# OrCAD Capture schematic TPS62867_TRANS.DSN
size D; title: TPS62867 2.4-V to 5.5-V Input, 6-A Synchronous Step-Down; rev: 1.1; note: Datasheet: SLUSDN8           EVM: NA
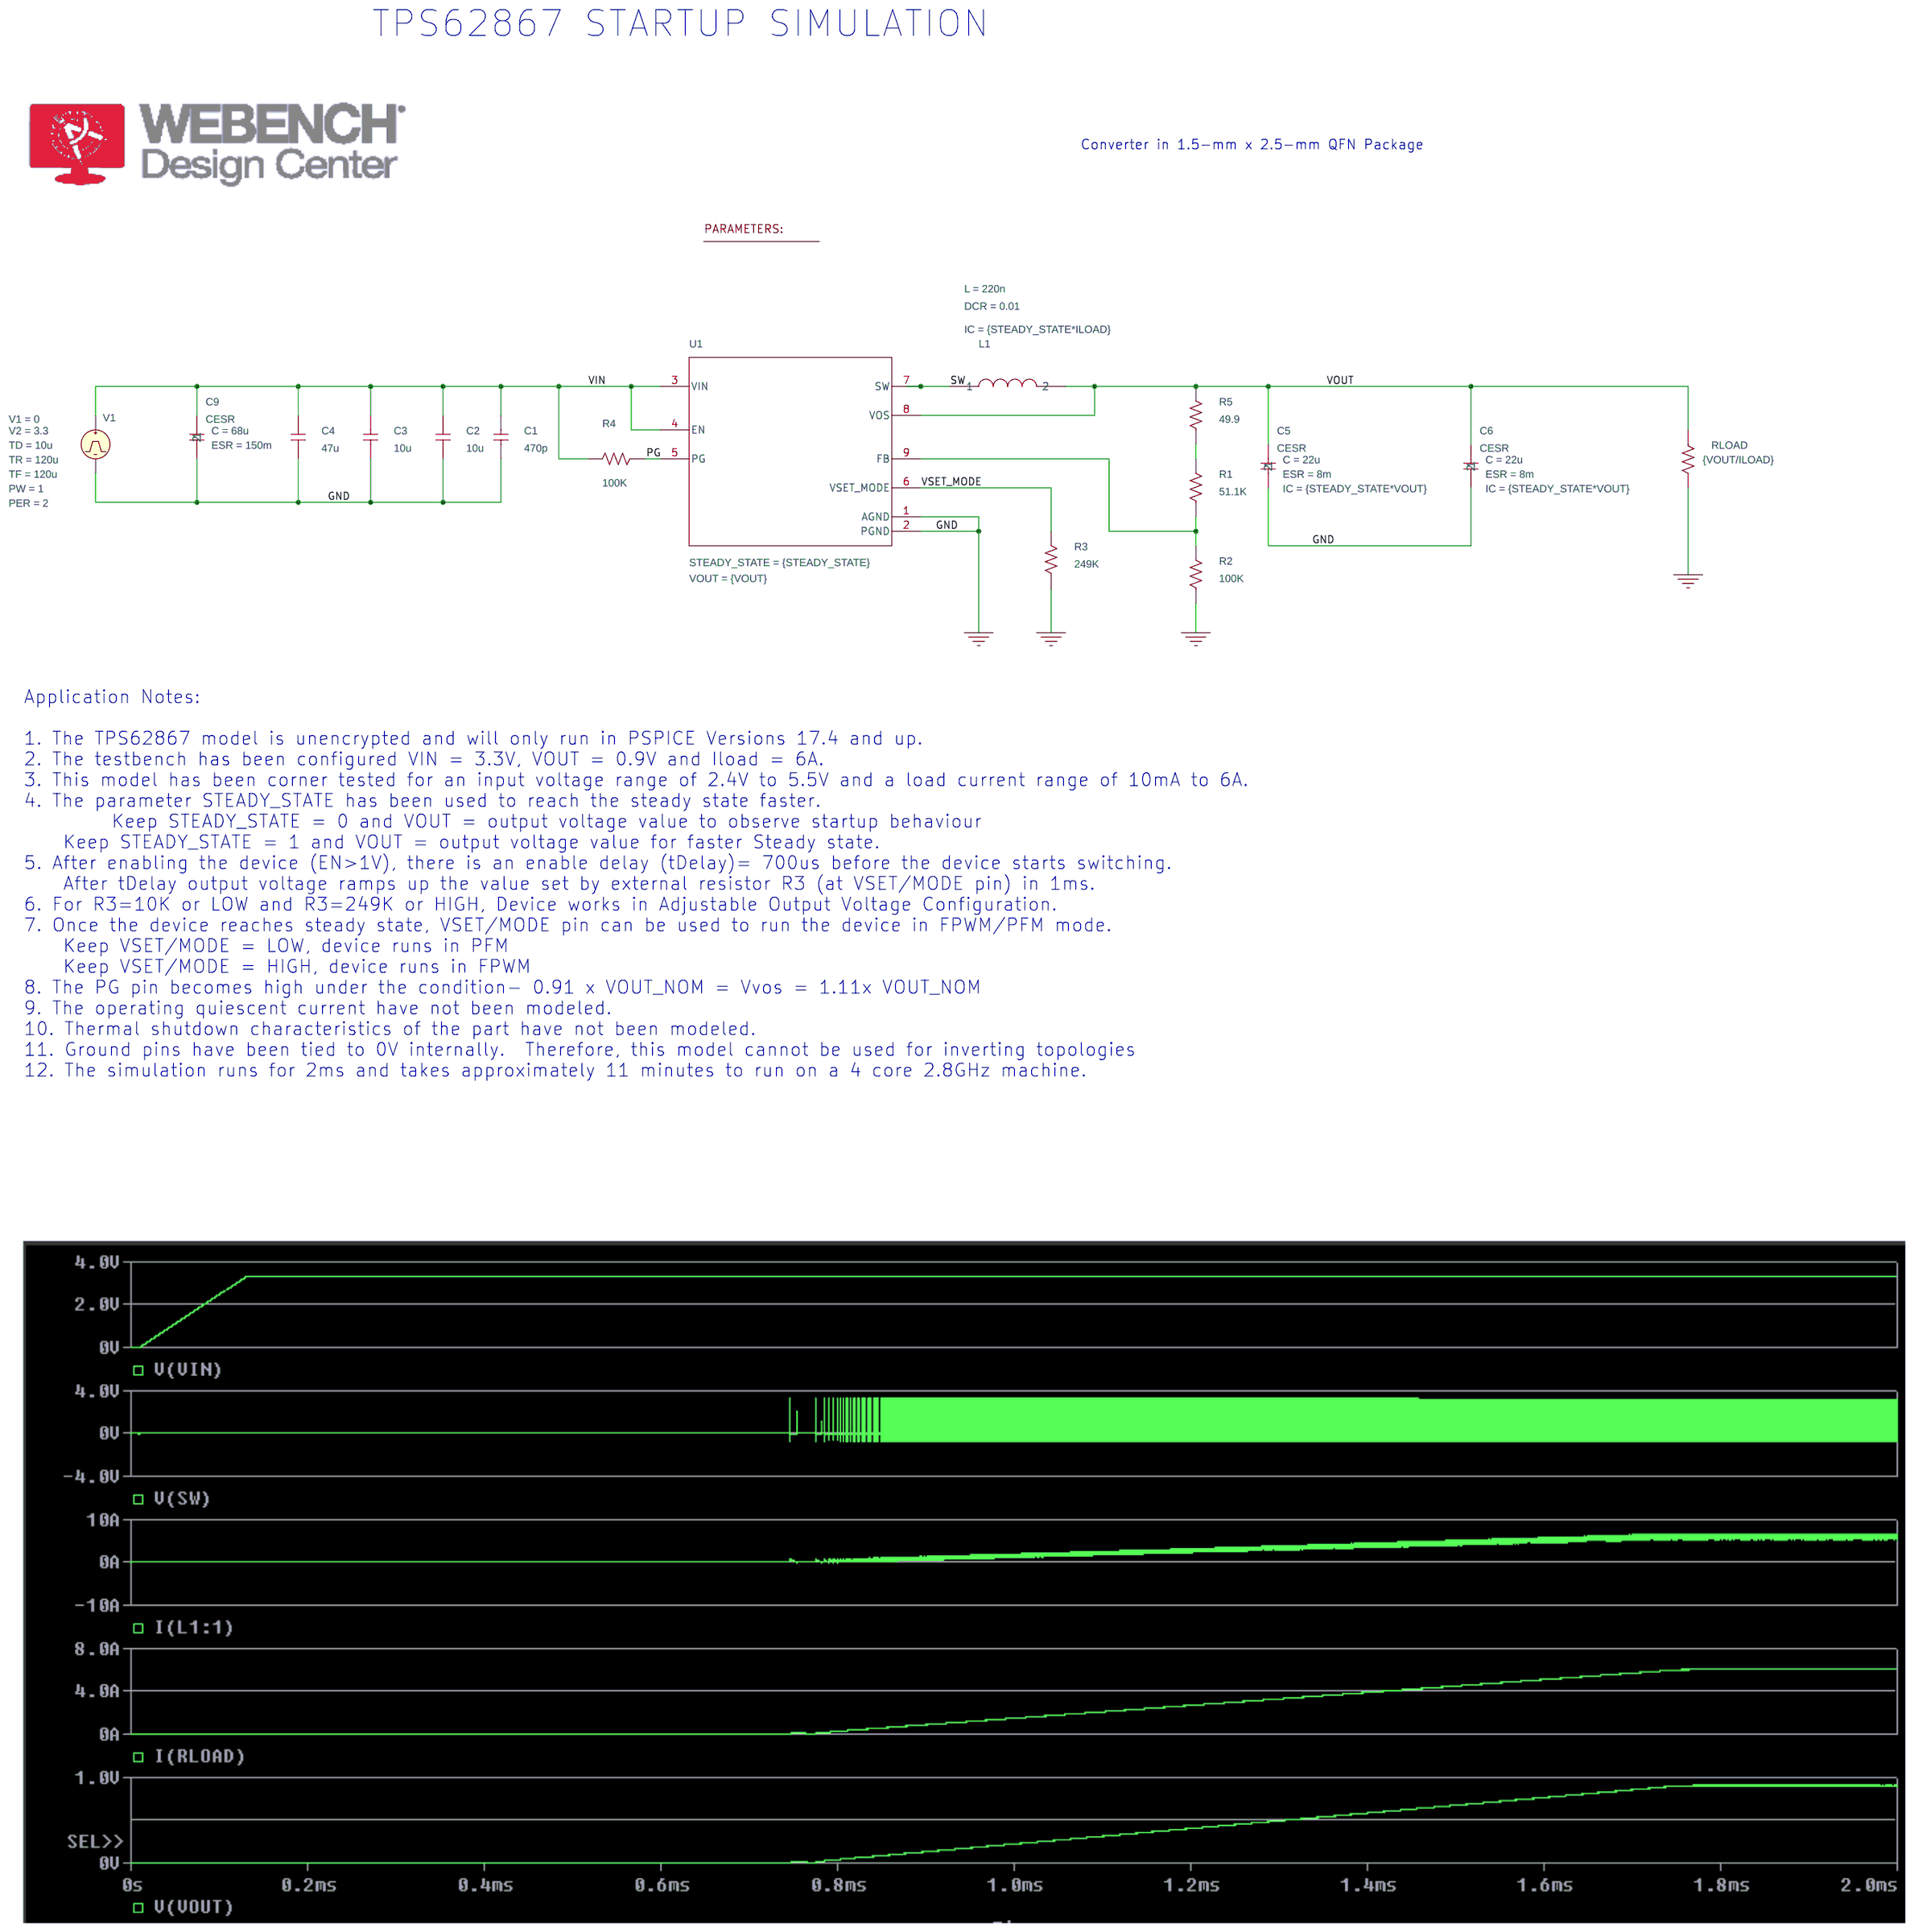
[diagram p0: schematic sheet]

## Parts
5  PARAM
C1  470p  [RAD/CK05]
C2  10u  [RAD/CK05]
C3  10u  [RAD/CK05]
C4  47u  [RAD/CK05]
C5  CESR
C6  CESR
C9  CESR
L1  LDCR
R1  51.1K  [AX/RC05]
R2  100K  [AX/RC05]
R3  249K  [AX/RC05]
R4  100K  [AX/RC05]
R5  49.9  [AX/RC05]
RLOAD  {VOUT/ILOAD}  [AX/RC05]
U1  Value  [RQY0009A-MFG]
V1  VPULSE

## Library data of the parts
5 = PARAM: ILOAD: 6; STEADY_STATE: 0; VOUT: 0.9
C1-C4 = C
C5 = CESR_1: C: 22u; ESL: 0; ESR: 8m; IC: {STEADY_STATE*VOUT}; PSpiceTemplate: X^@REFDES %1 %2 @MODEL PARAMS: ?C|C=@C||C=10U| ?ESR|ESR=@ESR||ESR=2M| ?ESL|ESL=@ESL||ESL=1N| ?IC|IC=@IC||IC=0|
C6 = CESR: C: 22u; ESL: 0; ESR: 8m; IC: {STEADY_STATE*VOUT}; PSpiceTemplate: X^@REFDES %1 %2 @MODEL PARAMS: ?C|C=@C||C=10U| ?ESR|ESR=@ESR||ESR=2M| ?ESL|ESL=@ESL||ESL=1N| ?IC|IC=@IC||IC=0|
C9 = CESR_2: C: 68u; ESR: 150m; PSpiceTemplate: X^@REFDES %1 %2 @MODEL PARAMS: ?C|C=@C||C=10U| ?ESR|ESR=@ESR||ESR=2M| ?ESL|ESL=@ESL||ESL=1N| ?IC|IC=@IC||IC=0|
L1 = LDCR: DCR: 0.01; IC: {STEADY_STATE*ILOAD}; L: 220n
R1-R5 RLOAD = R
U1 = TPS62867RQY_TRANS: ENABLE_FPWM_DURING_VOUT_CHANGE: 1; ENABLE_HICCUP: 1; ENABLE_OUTPUT_DISCHARGE: 1; HS_CURRENT_LIMIT: 7.7; LS_CURRENT_LIMIT: 6.5; PSpiceTemplate: X^@REFDES  %AGND %EN %FB %PG %PGND %SW %VIN %VOS %VSET_MODE @MODEL PARAMS: ?ENABLE_FPWM_DURING_VOUT_CHANGE|ENABLE_FPWM_DURING_VOUT_CHANGE=@ENABLE_FPWM_DURING_VOUT_CHANGE||ENABLE_FPWM_DURING_VOUT_CHANGE=1| ?ENABLE_HICCUP|ENABLE_HICCUP=@ENABLE_HICCUP||ENABLE_HICCUP=1| ?ENABLE_OUTPUT_DISCHARGE|ENABLE_OUTPUT_DISCHARGE=@ENABLE_OUTPUT_DISCHARGE||ENABLE_OUTPUT_DISCHARGE=1| ?HS_CURRENT_LIMIT|HS_CURRENT_LIMIT=@HS_CURRENT_LIMIT||HS_CURRENT_LIMIT=7.7| ?LS_CURRENT_LIMIT|LS_CURRENT_LIMIT=@LS_CURRENT_LIMIT||LS_CURRENT_LIMIT=6.5| ?STEADY_STATE|STEADY_STATE=@STEADY_STATE||STEADY_STATE=0| ?VOUT|VOUT=@VOUT||VOUT=0.9| ?VOUT_RAMP_SPEED|VOUT_RAMP_SPEED=@VOUT_RAMP_SPEED||VOUT_RAMP_SPEED=3|; STEADY_STATE: {STEADY_STATE}; VOUT: {VOUT}; VOUT_RAMP_SPEED: 3
V1 = VPULSE: PER: 2; PW: 1; TD: 10u; TF: 120u; TR: 120u; V1: 0; V2: 3.3

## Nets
VIN: C1.2 C2.2 C3.2 C4.2 C9.1 R4.2 U1.3(VIN) U1.4(EN) V1.1(+)
0: C1.1 C2.1 C3.1 C4.1 C5.2 C6.2 C9.2 R2.1 R3.1 RLOAD.2 U1.1(AGND) U1.2(PGND) V1.2(-)
PG: R4.1 U1.5(PG)
SW: L1.1 U1.7(SW)
VOUT: C5.1 C6.1 L1.2 R5.2 RLOAD.1 U1.8(VOS)
VSET_MODE: R3.2 U1.6(VSET_MODE)
N16508776: R1.2 R5.1
N16508814: R1.1 R2.2 U1.9(FB)

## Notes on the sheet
- TPS62867 STARTUP SIMULATION
- Converter in 1.5-mm x 2.5-mm QFN Package
- Application Notes:
  1. The TPS62867 model is unencrypted and will only run in PSPICE Versions 17.4 and up.
  2. The testbench has been configured VIN = 3.3V, VOUT = 0.9V and Iload = 6A.
  3. This model has been corner tested for an input voltage range of 2.4V to 5.5V and a load current range of 10mA to 6A.
  4. The parameter STEADY_STATE has been used to reach the steady state faster.
  	    Keep STEADY_STATE = 0 and VOUT = output voltage value to observe startup behaviour
      Keep STEADY_STATE = 1 and VOUT = output voltage value for faster Steady state.
  5. After enabling the device (EN>1V), there is an enable delay (tDelay)= 700us before the device starts switching.
      After tDelay output voltage ramps up the value set by external resistor R3 (at VSET/MODE pin) in 1ms.
  6. For R3=10K or LOW and R3=249K or HIGH, Device works in Adjustable Output Voltage Configuration.
  7. Once the device reaches steady state, VSET/MODE pin can be used to run the device in FPWM/PFM mode.
      Keep VSET/MODE = LOW, device runs in PFM
      Keep VSET/MODE = HIGH, device runs in FPWM
  8. The PG pin becomes high under the condition- 0.91 x VOUT_NOM = Vvos = 1.11x VOUT_NOM
  9. The operating quiescent current have not been modeled.
  10. Thermal shutdown characteristics of the part have not been modeled.
  11. Ground pins have been tied to 0V internally.  Therefore, this model cannot be used for inverting topologies
  12. The simulation runs for 2ms and takes approximately 11 minutes to run on a 4 core 2.8GHz machine.
